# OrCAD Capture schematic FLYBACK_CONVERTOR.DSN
size A
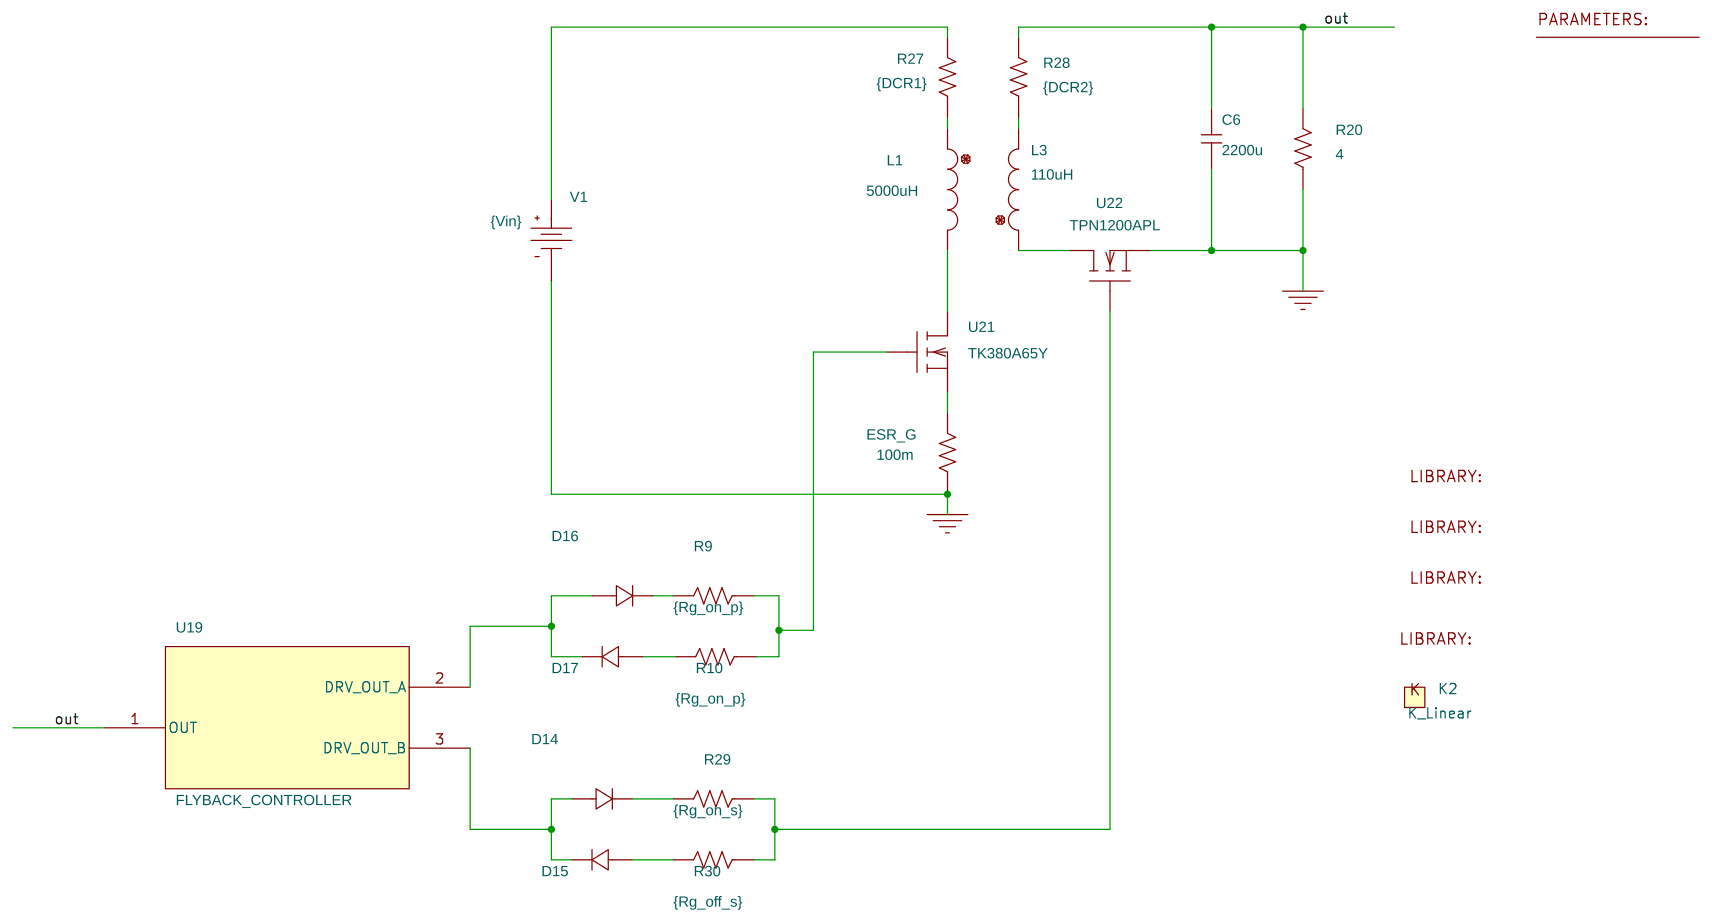
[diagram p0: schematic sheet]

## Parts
1  PARAM
C6  2200u  [cap196]
D14  Diode_nom
D15  Diode_nom
D16  Diode_nom
D17  Diode_nom
ESR_G  100m  [AXRC05]
K2  K_Linear
L1  5000uH  [DISC350x175LS200x100034]
L3  110uH  [DISC350x175LS200x100034]
LIB1  LIB
LIB2  LIB
LIB3  LIB
LIB4  LIB
R9  {Rg_on_p}  [AXRC05]
R10  {Rg_on_p}  [AXRC05]
R20  4  [AXRC05]
R27  {DCR1}  [AXRC05]
R28  {DCR2}  [AXRC05]
R29  {Rg_on_s}  [AXRC05]
R30  {Rg_off_s}  [AXRC05]
U19  FLYBACK_CONTROLLER
U21  TK380A65Y
U22  TPN1200APL
V1  VDC

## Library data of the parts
1 = PARAM: DCR1: 100m; DCR2: 100m; Fc: 100k; Rdrv_off_p: 0.5; Rdrv_off_s: 0.5; Rdrv_on_p: 5; Rg_off_p: 10; Rg_off_s: 0.1m; Rg_on_p: 20; Rg_on_s: 0.1m; Vdrv_H: 10; Vin: 380; Vout: 16
C6 = C
D14-D17 = Diode_nom
ESR_G R9 R10 R20 R27-R30 = R
K2 = K_Linear: COUPLING: 1; L1: L1; L2: L3
L1 L3 = L
LIB1 = LIB: FILENAME: ../../../Lib/TK380A65Y.lib
LIB2 = LIB: FILENAME: ../../../Lib/TPN1200APL.lib
LIB3 = LIB: FILENAME: ../../../Lib/diode_nom.lib
LIB4 = LIB: FILENAME: ../../../Lib/Flyback_controller.lib
U19 = FLYBACK_CONTROLLER
U21 = TK380A65Y
U22 = TPN1200APL
V1 = VDC: DC: {Vin}

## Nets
0: C6.1 ESR_G.1 R20.1 U22.0(s) V1.1(-)
out: C6.2 R20.2 R28.2 U19.1(OUT)
N2185786: R27.2 V1.0(+)
N2185890: L1.1 R27.1
N2185896: L3.2 R28.1
N2185994: L1.2 U21.2(d)
N2186000: L3.1 U22.2(d)
N2186052: R29.1 R30.1 U22.1(g)
N2186076: R9.1 R10.1 U21.1(g)
N2186084: ESR_G.2 U21.0(s)
N2186180: D16.0(1) D17.1(2) U19.2(DRV_OUT_A)
N2186190: D16.1(2) R9.2
N2186324: D14.0(1) D15.1(2) U19.3(DRV_OUT_B)
N2186368: D14.1(2) R29.2
N2186436: D15.0(1) R30.2
N2187109: D17.0(1) R10.2
